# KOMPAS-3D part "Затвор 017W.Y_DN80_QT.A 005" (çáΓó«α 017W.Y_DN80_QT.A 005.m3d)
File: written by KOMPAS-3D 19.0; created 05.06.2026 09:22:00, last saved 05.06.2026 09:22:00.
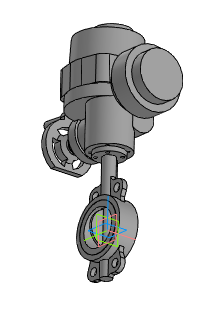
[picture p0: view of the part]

Document properties: Автор: Энергия; Полное имя файла: ..\..\..\3d для проектировщиков\x.x Тип 017W.Y(S) Затвор дисковый поворотный межфланцевый\Затвор 017W.Y(S)_DN32-DN1200_QT.A_MT903.A\Затвор 017W.Y_DN80_QT.A 005.a3d

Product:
- Part/product: Затвор 017W.Y_DN80_QT.A 005
    Масса: 39.703

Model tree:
1. Операция без истории:1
